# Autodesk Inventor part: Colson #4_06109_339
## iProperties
Shininess: 64.0
Length Units: 11272
Angle Units: 11279
Time Units: 11290
Mass Units: 11286
Length Display Precision: 3
Angle Display Precision: 2
Compacted: True
Part Number: Colson #4_06109_339
Document SubType Name: Modeling
Created: 2003-06
Designer: ARennick
Manufacturer: Standard
Standards Organization: Custom
Description: Series 4 (1250lb) Swivel Caster, Standard Mount Plate, 6 dia, Phenolic wheel.
Catalog Web Link: www.colsoncaster.com
Density: 0.0
Volumn: 0.0
Area: 0.0
PropertySet Name: Model Information
Control State: 0
Master: False
Checked Out: False
Author: ARennick
Comments: These are basically 5 sizes of caster with different part numbers used for the materials. This file has a fixed wheel angle of 90 deg, and creates a filename automatically. Thanks as always to Charles
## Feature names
1. Top Plate [Extrusion]
2. Bearing Shape [Revolution]
3. Bearing Fillets [Fillet]
4. Wheel Flange Cut [Extrusion]
5. Extrusion5
6. Extrusion6
7. Mirror2
8. Revolution2
9. Fillet2
